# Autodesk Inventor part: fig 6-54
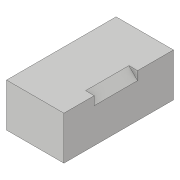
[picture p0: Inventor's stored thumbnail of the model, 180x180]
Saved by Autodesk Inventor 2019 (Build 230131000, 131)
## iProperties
Created: 2018-03
Part Number: fig 6-54
Material: Generic
Document SubType Name: Modeling
Designer: CADCIM 00
Density: 1 g/cm^3
Appearance: Default
Author: CADCIM 00
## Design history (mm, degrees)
sketch "Sketch1"
  geometry: L1 (0, 0)-(13.237, 0); L2 (13.237, 0)-(13.237, -25.282); L3 (13.237, -25.282)-(0, -25.282); L4 (0, -25.282)-(0, 0)
  constraints: 8 end point, 2 parallel, 1 horizontal, 1 perpendicular
extrude "Extrusion1" new body sketch "Sketch1" distance "d0" = 10; taper "d1" = 0 deg
chamfer "Chamfer1" distance "d2" = 2; stored, may be unused: second distance "d3" = 2, angle "d4" = 45 deg; dims "d5" = 7, "d6" = 10, "d7" = 8.28246
body "Solid1"
